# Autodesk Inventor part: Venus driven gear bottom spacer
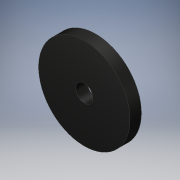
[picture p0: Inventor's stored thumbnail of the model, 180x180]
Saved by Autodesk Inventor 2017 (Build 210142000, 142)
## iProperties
Created: 2016-07
Part Number: Venus driven gear bottom spacer
Material: Generic
Document SubType Name: Modeling
Designer: Stan
Density: 1 g/cm^3
Appearance: Glossy - Black
Author: Stan
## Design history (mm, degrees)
sketch "Sketch1"
  geometry: C1 r 2.413 at (0, 0); C2 r 12.7 at (0, 0); 1 further point
  constraints: 2 centre point, 2 coincident
  dimensions: "d0" = 4.826 diameter of C1; "d1" = 25.4 diameter of C2
extrude "Extrusion1" new body sketch "Sketch1" distance "d2" = 3.175; taper "d3" = 0 deg
body "Solid1"
